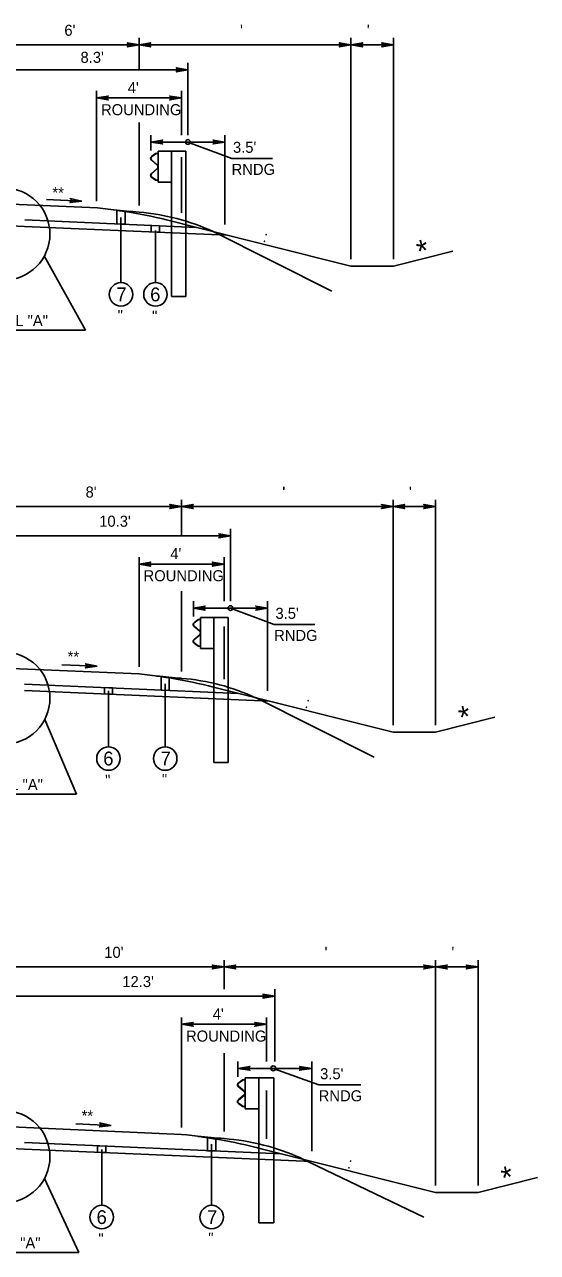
# Model space of a CAD drawing. Extents: x -540 to 1231, y -564 to 421.
# Drawn here: x 610.8 to 675.8, y 70.6 to 226.2 of the extents above; entities that cross this region are included whole.
import ezdxf

# ---------------------------------------------------------------- set-up
doc = ezdxf.new("R2010")
doc.units = 0
doc.layers.add('1', color=7, linetype='Continuous')
doc.layers.add('Des_ Drain_ Ftrs', color=7, linetype='Continuous')

msp = doc.modelspace()

# ---------------------------------------------------------------- linework, layer by layer
at = {"layer": '1'}
for p, q in [((625.28, 220.53), (625.28, 224.55)), ((652.15, 196.51), (652.15, 224.55)), ((657.54, 196.51), (657.54, 224.55)), ((609.12, 223.67), (625.28, 223.67)), ((625.28, 223.67), (652.15, 223.67)), ((652.15, 223.67), (657.54, 223.67)), ((631.48, 212.23), (631.48, 221.39)), ((609.12, 220.51), (631.48, 220.51)), ((619.89, 203.87), (619.89, 217.82)), ((619.89, 216.94), (630.67, 216.94)), ((630.67, 212.23), (630.67, 217.82)), ((625.28, 203.32), (625.28, 213.84)), ((626.78, 210.28), (626.78, 212.23)), ((636.17, 200.89), (636.17, 212.23)), ((626.78, 211.35), (636.17, 211.35)), ((631.48, 211.35), (637.03, 209.28)), ((626.85, 209.06), (627.58, 208.43)), ((627.38, 209.89), (626.87, 209.5)), ((626.87, 209.09), (627.6, 208.45)), ((627.39, 209.86), (626.88, 209.47)), ((627.7, 209.94), (627.38, 209.89)), ((627.7, 209.91), (627.39, 209.86)), ((627.7, 210.17), (627.7, 206.24)), ((627.7, 210.17), (629.38, 210.17)), ((629.38, 210.17), (629.38, 191.77)), ((631.21, 210.17), (629.38, 210.17)), ((630.67, 202.36), (630.67, 209.42)), ((631.21, 210.17), (631.21, 191.77)), ((637.03, 209.28), (642.19, 209.28)), ((627.58, 207.98), (626.85, 207.34)), ((627.6, 207.96), (626.87, 207.32)), ((627.67, 208.24), (627.67, 208.17)), ((627.7, 208.24), (627.7, 208.17)), ((626.87, 206.91), (627.38, 206.52)), ((626.88, 206.94), (627.39, 206.55)), ((627.38, 206.52), (627.7, 206.47)), ((627.39, 206.55), (627.7, 206.5)), ((627.7, 206.24), (629.38, 206.24)), ((618.02, 203.86), (613.53, 204.05)), ((620, 202.99), (609.12, 203.46)), ((610.76, 200.66), (582.17, 201.91)), ((632.57, 200.53), (610.78, 201.47)), ((622.99, 201.78), (622.99, 193.52)), ((626.78, 202.22), (626.78, 202.22)), ((630.77, 200.98), (652.15, 195.63)), ((636.47, 199.55), (610.76, 200.66)), ((627.36, 200.15), (627.36, 193.52)), ((634.67, 199.99), (649.72, 192.46)), ((613.27, 196.9), (618.49, 187.51)), ((665.08, 197.51), (657.54, 195.63)), ((652.15, 195.63), (657.54, 195.63)), ((631.21, 191.77), (629.38, 191.77)), ((599.71, 187.51), (618.49, 187.51)), ((609.12, 165.12), (630.67, 165.12)), ((630.67, 161.42), (630.67, 166)), ((630.67, 165.12), (657.49, 165.12)), ((657.49, 137.42), (657.49, 166)), ((657.49, 165.12), (662.88, 165.12)), ((662.88, 137.42), (662.88, 166)), ((636.87, 153.14), (636.87, 162.3)), ((609.12, 161.42), (636.87, 161.42)), ((625.28, 144.79), (625.28, 158.72)), ((625.28, 157.84), (636.06, 157.84)), ((636.06, 153.14), (636.06, 158.72)), ((630.67, 144.23), (630.67, 154.39)), ((632.17, 151.19), (632.17, 153.14)), ((641.56, 141.78), (641.56, 153.14)), ((632.17, 152.26), (641.56, 152.26)), ((633.09, 151.08), (633.09, 147.14)), ((633.09, 151.08), (634.77, 151.08)), ((634.77, 151.08), (634.77, 132.68)), ((636.6, 151.08), (634.77, 151.08)), ((636.6, 151.08), (636.6, 132.68)), ((636.87, 152.26), (642.42, 150.19)), ((632.24, 149.97), (632.97, 149.33)), ((632.77, 150.79), (632.25, 150.4)), ((632.26, 149.99), (632.99, 149.36)), ((632.78, 150.76), (632.27, 150.38)), ((633.09, 150.85), (632.77, 150.79)), ((633.09, 150.82), (632.78, 150.76)), ((636.06, 143.26), (636.06, 149.91)), ((642.42, 150.19), (647.58, 150.19)), ((632.97, 148.88), (632.24, 148.25)), ((632.99, 148.86), (632.26, 148.23)), ((633.06, 149.15), (633.06, 149.07)), ((633.09, 149.15), (633.09, 149.07)), ((632.25, 147.82), (632.77, 147.43)), ((632.27, 147.84), (632.78, 147.46)), ((632.77, 147.43), (633.09, 147.37)), ((632.78, 147.46), (633.09, 147.4)), ((633.09, 147.14), (634.77, 147.14)), ((619.99, 144.88), (615.5, 145.08)), ((625.28, 143.91), (609.12, 144.61)), ((637.89, 141.44), (610.76, 142.62)), ((641.81, 140.46), (610.76, 141.81)), ((621.4, 141.75), (621.4, 134.67)), ((628.6, 142.65), (628.6, 134.67)), ((632.17, 143.13), (632.17, 143.13)), ((636.06, 141.9), (657.49, 136.54)), ((640.06, 140.9), (655.11, 133.37)), ((613.32, 138.14), (617.37, 128.67)), ((670.42, 138.42), (662.88, 136.54)), ((657.49, 136.54), (662.88, 136.54)), ((636.6, 132.68), (634.77, 132.68)), ((598.58, 128.67), (617.37, 128.67)), ((636.06, 103.93), (636.06, 107.63)), ((662.88, 79.04), (662.88, 107.63)), ((668.27, 79.04), (668.27, 107.63)), ((609.12, 106.75), (636.06, 106.75)), ((636.06, 106.75), (662.88, 106.75)), ((662.88, 106.75), (668.27, 106.75)), ((609.12, 103.05), (642.48, 103.05)), ((642.48, 94.78), (642.48, 103.93)), ((630.67, 86.41), (630.67, 100.36)), ((641.44, 94.78), (641.44, 100.36)), ((630.67, 99.48), (641.44, 99.48)), ((636.06, 85.87), (636.06, 95.83)), ((637.79, 92.82), (637.79, 94.78)), ((637.79, 93.9), (647.18, 93.9)), ((642.31, 93.9), (648.07, 91.82)), ((647.18, 83.41), (647.18, 94.78)), ((638.41, 92.43), (637.88, 92.04)), ((638.43, 92.4), (637.9, 92.02)), ((638.74, 92.48), (638.41, 92.43)), ((638.74, 92.45), (638.43, 92.4)), ((638.74, 92.71), (638.74, 88.78)), ((638.74, 92.71), (640.49, 92.71)), ((640.49, 92.71), (640.49, 74.31)), ((642.38, 92.71), (640.49, 92.71)), ((642.38, 92.71), (642.38, 74.31)), ((637.86, 91.61), (638.62, 90.97)), ((638.62, 90.52), (637.86, 89.89)), ((637.88, 91.63), (638.64, 90.99)), ((638.64, 90.5), (637.88, 89.86)), ((638.71, 90.78), (638.71, 90.71)), ((638.74, 90.78), (638.74, 90.71)), ((641.44, 84.95), (641.44, 91.1)), ((648.07, 91.82), (653.42, 91.82)), ((637.88, 89.45), (638.41, 89.06)), ((637.9, 89.48), (638.43, 89.09)), ((638.41, 89.06), (638.74, 89.01)), ((638.43, 89.09), (638.74, 89.04)), ((638.74, 88.78), (640.49, 88.78)), ((630.67, 85.53), (609.12, 86.47)), ((621.76, 86.66), (617.27, 86.86)), ((643.28, 83.06), (610.76, 84.48)), ((634.49, 84.28), (634.49, 76.52)), ((637.79, 84.77), (637.79, 84.77)), ((610.76, 83.67), (609.12, 83.74)), ((647.2, 82.08), (610.76, 83.67)), ((620.55, 83.61), (620.55, 76.52)), ((641.44, 83.52), (662.88, 78.16)), ((645.8, 82.53), (661.41, 75.01)), ((613.29, 79.95), (617.65, 70.56)), ((675.8, 80.04), (668.27, 78.16)), ((662.88, 78.16), (668.27, 78.16)), ((642.38, 74.31), (640.49, 74.31)), ((598.86, 70.56), (617.65, 70.56))]:
    msp.add_line(p, q, dxfattribs=at)
for points in [[(622.47, 202.68), (623.51, 202.53), (623.51, 200.92), (622.47, 200.96)], [(626.83, 200.78), (627.87, 200.73), (627.87, 199.92), (626.83, 199.97)], [(628.08, 143.56), (629.12, 143.4), (629.12, 141.82), (628.08, 141.87)], [(620.88, 142.18), (621.93, 142.13), (621.93, 141.33), (620.88, 141.37)], [(620.03, 84.07), (621.07, 84.03), (621.07, 83.22), (620.03, 83.26)], [(633.97, 85.1), (635.01, 84.93), (635.01, 83.42), (633.97, 83.46)]]:
    msp.add_lwpolyline(points, close=True, dxfattribs=at)
for centre, radius in [((631.48, 211.35), 0.3), ((608.14, 199.68), 5.84), ((622.99, 192.03), 1.49), ((627.36, 192.03), 1.49), ((636.87, 152.26), 0.3), ((608.14, 140.83), 5.84), ((621.4, 133.18), 1.49), ((628.6, 133.18), 1.49), ((608.14, 82.69), 5.84), ((620.55, 75.04), 1.49), ((634.49, 75.04), 1.49)]:
    msp.add_circle(centre, radius, dxfattribs=at)
for centre, radius, start, end in [((627.03, 209.27), 0.278, 126.9799, 229.021), ((627.03, 209.27), 0.249, 126.9799, 229.021), ((627.03, 207.13), 0.278, 130.979, 233.0201), ((627.03, 207.13), 0.249, 130.979, 233.0201), ((627.42, 208.24), 0.249, 0, 49.0365), ((627.42, 208.17), 0.249, 310.9635, 0), ((627.42, 208.24), 0.278, 0, 49.0365), ((627.42, 208.17), 0.278, 310.9635, 0), ((613.11, 136.15), 67.19, 74.7602, 84.1188), ((614.46, 101.78), 101.24, 83.8633, 85.6775), ((623.16, 175.16), 27.37, 65.1374, 85.5513), ((632.42, 150.18), 0.278, 126.9799, 229.021), ((632.42, 150.18), 0.249, 126.9799, 229.021), ((632.42, 148.04), 0.278, 130.979, 233.0201), ((632.42, 148.04), 0.249, 130.979, 233.0201), ((632.81, 149.15), 0.249, 0, 49.0365), ((632.81, 149.07), 0.249, 310.9635, 0), ((632.81, 149.15), 0.278, 0, 49.0365), ((632.81, 149.07), 0.278, 310.9635, 0), ((618.4, 77.07), 67.19, 74.7602, 84.1188), ((619.85, 42.69), 101.24, 83.8633, 85.6775), ((628.55, 116.06), 27.37, 65.1374, 85.5513), ((623.78, 18.69), 67.19, 74.7602, 84.1188)]:
    msp.add_arc(centre, radius, start, end, dxfattribs=at)
msp.add_ellipse((642.31, 93.9), major_axis=(-0.311, 0), ratio=0.964041, dxfattribs=at)
for centre, major_axis, start_param, end_param in [((638.05, 91.82), (-0.288, 0), 5.35781, 7.138763), ((638.05, 91.82), (-0.258, 0), 5.35781, 7.138763), ((638.45, 90.78), (0.258, 0), 0, 0.855848), ((638.45, 90.71), (0.258, 0), 5.427337, 6.283185), ((638.45, 90.78), (0.288, 0), 0, 0.855848), ((638.45, 90.71), (0.288, 0), 5.427337, 6.283185), ((638.05, 89.67), (-0.288, 0), 5.427608, 7.208561), ((638.05, 89.67), (-0.258, 0), 5.427608, 7.208561), ((624.84, -15.68), (105.02, 0), 1.463691, 1.495354), ((633.86, 57.7), (28.39, 0), 1.136862, 1.493152)]:
    msp.add_ellipse(centre, major_axis=major_axis, ratio=0.964041, start_param=start_param, end_param=end_param, dxfattribs=at)
at = {"layer": 'Des_ Drain_ Ftrs'}
for points in [[(625.28, 223.67), (623.79, 223.42), (624.09, 223.67), (623.79, 223.92)], [(625.28, 223.67), (626.77, 223.42), (626.47, 223.67), (626.77, 223.92)], [(652.15, 223.67), (650.67, 223.42), (650.96, 223.67), (650.67, 223.92)], [(652.15, 223.67), (653.64, 223.42), (653.35, 223.67), (653.64, 223.92)], [(657.54, 223.67), (656.05, 223.42), (656.35, 223.67), (656.05, 223.92)], [(631.48, 220.51), (629.99, 220.26), (630.28, 220.51), (629.99, 220.76)], [(619.89, 216.94), (621.38, 216.69), (621.08, 216.94), (621.38, 217.18)], [(630.67, 216.94), (629.18, 216.69), (629.47, 216.94), (629.18, 217.18)], [(626.78, 211.35), (628.27, 211.11), (627.98, 211.35), (628.27, 211.6)], [(636.17, 211.35), (634.68, 211.11), (634.98, 211.35), (634.68, 211.6)], [(618.02, 203.86), (616.52, 203.67), (616.83, 203.91), (616.54, 204.17)], [(630.67, 165.12), (629.18, 164.87), (629.47, 165.12), (629.18, 165.37)], [(630.67, 165.12), (632.16, 164.87), (631.86, 165.12), (632.16, 165.37)], [(657.49, 165.12), (656.01, 164.87), (656.3, 165.12), (656.01, 165.37)], [(657.49, 165.12), (658.98, 164.87), (658.69, 165.12), (658.98, 165.37)], [(662.88, 165.12), (661.39, 164.87), (661.69, 165.12), (661.39, 165.37)], [(636.87, 161.42), (635.38, 161.17), (635.67, 161.42), (635.38, 161.66)], [(625.28, 157.84), (626.77, 157.59), (626.47, 157.84), (626.77, 158.09)], [(636.06, 157.84), (634.57, 157.59), (634.86, 157.84), (634.57, 158.09)], [(632.17, 152.26), (633.66, 152.01), (633.37, 152.26), (633.66, 152.51)], [(641.56, 152.26), (640.07, 152.01), (640.36, 152.26), (640.07, 152.51)], [(619.99, 144.88), (618.49, 144.7), (618.8, 144.93), (618.51, 145.19)], [(636.06, 106.75), (634.57, 106.51), (634.86, 106.75), (634.57, 107)], [(636.06, 106.75), (637.54, 106.51), (637.25, 106.75), (637.54, 107)], [(662.88, 106.75), (661.39, 106.51), (661.69, 106.75), (661.39, 107)], [(662.88, 106.75), (664.37, 106.51), (664.07, 106.75), (664.37, 107)], [(668.27, 106.75), (666.78, 106.51), (667.07, 106.75), (666.78, 107)], [(642.48, 103.05), (640.99, 102.8), (641.29, 103.05), (640.99, 103.3)], [(630.67, 99.48), (632.16, 99.23), (631.86, 99.48), (632.16, 99.73)], [(641.44, 99.48), (639.96, 99.23), (640.25, 99.48), (639.96, 99.73)], [(637.79, 93.9), (639.34, 93.65), (639.03, 93.9), (639.34, 94.14)], [(647.18, 93.9), (645.63, 93.65), (645.94, 93.9), (645.63, 94.14)], [(621.76, 86.66), (620.27, 86.48), (620.57, 86.71), (620.29, 86.97)]]:
    msp.add_lwpolyline(points, close=True, dxfattribs=at)

# ---------------------------------------------------------------- texts
at = {"layer": '1'}
for s, height, p in [("6'", 1.4, (615.81, 224.82)), ("  '", 1.4, (637.05, 224.82)), (" '", 1.4, (653.65, 224.82)), ("8.3'", 1.4, (617.86, 221.39)), ("4'", 1.4, (623.85, 217.55)), ('ROUNDING', 1.4, (620.46, 214.75)), ("3.5'", 1.4, (637.19, 209.98)), ('RNDG', 1.4, (637.02, 207.18)), ('7', 1.75, (622.4, 191.16)), ('6', 1.75, (626.69, 191.15)), (' "', 1.4, (622.05, 188.67)), (' "', 1.4, (626.41, 188.57)), ('SEE DETAIL "A"', 1.4, (599.81, 188.01)), ("8'", 1.4, (618.5, 166.27)), ("  '", 1.4, (642.38, 166.27)), ("  '", 1.4, (642.44, 166.27)), (" '", 1.4, (658.99, 166.27)), ("10.3'", 1.4, (620.23, 162.57)), ("4'", 1.4, (629.24, 158.46)), ('ROUNDING', 1.4, (625.85, 155.66)), ("3.5'", 1.4, (642.58, 150.89)), ('RNDG', 1.4, (642.41, 148.09)), ('6', 1.75, (620.74, 132.31)), ('7', 1.75, (628.01, 132.31)), (' "', 1.4, (620.46, 129.73)), (' "', 1.4, (627.66, 129.82)), ('SEE DETAIL "A"', 1.4, (599.17, 129.18)), ("10'", 1.4, (620.87, 107.91)), ("  '", 1.4, (647.77, 107.91)), (" '", 1.4, (664.38, 107.91)), ("12.3'", 1.4, (623.16, 104.2)), ("4'", 1.4, (634.63, 100.09)), ('ROUNDING', 1.4, (631.24, 97.29)), ("3.5'", 1.4, (648.24, 92.52)), ('RNDG', 1.4, (648.06, 89.72)), ('6', 1.75, (619.89, 74.16)), ('7', 1.75, (633.9, 74.16)), ('SEE DETAIL "A"', 1.4, (598.87, 71.06)), (' "', 1.4, (619.61, 71.58)), (' "', 1.4, (633.54, 71.68))]:
    msp.add_text(s, height=height, dxfattribs=at).set_placement(p)
for s, height, rotation, p in [('**', 1.4, 357.2166, (614.24, 204.26)), (' : ', 1.4, 345.7718, (640.41, 198.86)), ('*', 2.8, 12.8479, (660.86, 196.04)), ('**', 1.4, 357.2168, (616.18, 145.44)), (' : ', 1.4, 345.7718, (645.73, 139.77)), ('*', 2.8, 12.8479, (666.2, 136.94)), ('**', 1.4, 357.2166, (617.95, 87.22)), (' : ', 1.4, 345.7718, (651.11, 81.39)), ('*', 2.8, 12.8479, (671.58, 78.56))]:
    msp.add_text(s, height=height, rotation=rotation, dxfattribs=at).set_placement(p)

doc.saveas('drawing.dxf')
